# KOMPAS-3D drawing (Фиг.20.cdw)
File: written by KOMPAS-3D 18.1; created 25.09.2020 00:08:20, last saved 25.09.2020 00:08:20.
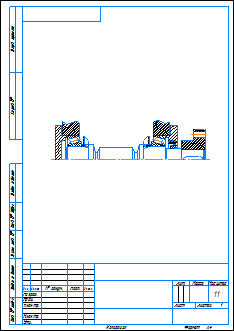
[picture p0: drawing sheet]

Sheet 1: A4, portrait

Document properties: Автор: user; Полное имя файла: C:\Users\user\Desktop\Задания\Фиг.20.cdw

Title block, sheet 1: scale: 1:1; Количество листов документа: 1; Форматы листов документа: A4

Dimensions and other numbers on the sheet: 1:1; 1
